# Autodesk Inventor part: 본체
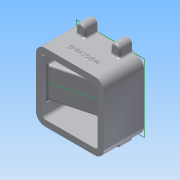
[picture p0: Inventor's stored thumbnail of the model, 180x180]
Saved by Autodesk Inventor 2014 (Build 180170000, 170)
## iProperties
Created: 2018-01
Part Number: 본체
Material: 알루미늄 6061
Document SubType Name: Modeling
Designer: net
Mass: 998.942 g
Surface Area: 839.391 cm^2
Volume: 368.613 cm^3
Density: 2.71 g/cm^3
Appearance: 알루미늄 - 평지
Author: net
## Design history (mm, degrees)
sketch "스케치1"
  geometry: L1 (-55, -55)-(55, -55); L2 (55, -55)-(55, 55); L3 (55, 55)-(-55, 55); L4 (-55, 55)-(-55, -55); L5 (-55, -55)-(55, 55); L6 (55, -55)-(-55, 55); 1 further point
  constraints: 12 end point, 2 midpoint, 2 parallel, 1 horizontal, 1 perpendicular
  dimensions: "d0" = 110 distance of L3.end L2.end; "d1" = 110 distance of L2.end L1.end
extrude "돌출1" new body sketch "스케치1" distance "d2" = 65; taper "d3" = 0 deg
sketch "스케치2"
  geometry: L1 (55, 55)-(-55, 55) reference; L2 (-55, 55)-(-55, -55) reference; L3 (-55, -55)-(55, -55) reference; L4 (55, -55)-(55, 55) reference; 1 further point
sketch "스케치3"
  geometry: L1 (-45, -45)-(45, -45); L2 (45, -45)-(45, 45); L3 (45, 45)-(-45, 45); L4 (-45, 45)-(-45, -45); L5 (-45, -45)-(45, 45); L6 (45, -45)-(-45, 45); 1 further point
  constraints: 12 end point, 2 midpoint, 2 parallel, 1 horizontal, 1 perpendicular
  dimensions: "d4" = 90 distance of L3.end L2.end; "d5" = 90 distance of L2.end L1.end
extrude "돌출2" cut sketch "스케치3" distance "d6" = 65; taper "d7" = 0 deg
sketch "스케치4"
  geometry: L1 (55, 55)-(-55, 55) reference; L2 (-55, 55)-(-55, -55) reference; L3 (-55, -55)-(55, -55) reference; L4 (-55, 0)-(-55, 25); L5 (-35.5, 65)-(-35.5, 55); L6 (-20.5, 65)-(-20.5, 55); L7 (0, 55)-(0, -55); L8 (-28, 65)-(28, 65); L9 (20.5, 65)-(20.5, 55); L10 (35.5, 65)-(35.5, 55); L11 (-55, -55)-(-28, -55); L12 (-28, -55)-(-28, -65); L13 (-35.5, -65)-(-35.5, -55); L14 (-20.5, -65)-(-20.5, -55); L15 (35.5, -65)-(35.5, -55); L16 (20.5, -65)-(20.5, -55); A1 r 7.5 centre (-28, 65) between (-20.5, 65) and (-35.5, 65); A2 r 7.5 centre (28, 65) between (35.5, 65) and (20.5, 65); A3 r 7.5 centre (-28, -65) between (-35.5, -65) and (-20.5, -65); A4 r 7.5 centre (28, -65) between (20.5, -65) and (35.5, -65); 1 further point
  constraints: 26 end point, 11 point on line, 8 point on circle, 8 tangent, 6 perpendicular, 4 centre point, 3 midpoint, 3 parallel, 2 coincident
  dimensions: "d9" = 25 distance of L4.start L4.end; "d11" = 27 distance from line of L2 L8.start; "d12" = 7.5 radius of A1; "d13" = 10 distance of L6.start L6.end; "d14" = 56 distance of L8.start L8.end; "d15" = 15 diameter of A2; "d16" = 27 distance of L2.end L11.end; "d17" = 10 distance of L11.end L12.end; "d18" = 15 diameter of A3; "d20" = 15 diameter of A4
extrude "돌출3" join sketch "스케치4" distance "d21" = 20; taper "d22" = 0 deg
sketch "스케치5"
  geometry: L1 (-45, 0)-(-45, 65) reference; L2 (-45, 8.564)-(35, 30); L3 (-45, 8.564)-(-45, 65); L4 (55, 0)-(-55, 0) reference; L5 (-45, 8.564)-(-55, 8.564); L6 (-55, 8.564)-(-55, 26.564); L7 (-55, 26.564)-(-45, 26.564); L8 (-45, 26.564)-(-6.286, 36.938); L9 (-6.286, 36.938)-(-6.286, 65); L10 (-45, 65)-(35, 65); L11 (35, 65)-(35, 30); 2 further points
  constraints: 18 end point, 3 perpendicular, 3 point on line, 2 parallel, 1 collinear
  dimensions: "d23" = 105 deg angle of L1 L2; "d25" = 18 distance of L5.end L6.end; "d26" = 75 deg angle of L1 L8 (derived); "d28" = 20 distance of point (55, 65) L10.end; "d29" = 30 distance from line of L4 L2.end
extrude "돌출4" join sketch "스케치5" stored distance "d30" = 50; taper "d31" = 0 deg
sketch "스케치6"
  geometry: 1 further point
sketch "스케치7"
  geometry: L1 (0, 65)-(110, 65) reference; C1 r 7.5 at (55, 65); 1 further point
  constraints: 1 centre point, 1 midpoint
  dimensions: "d32" = 15 diameter of C1
extrude "돌출5" cut sketch "스케치7" distance "d33" = 19; taper "d34" = 0 deg
sketch "스케치8"
  geometry: L1 (47.5, 65)-(62.5, 65) reference; A1 r 7.5 centre (55, 65) between (47.5, 65) and (62.5, 65) reference; 1 further point
sketch "스케치9"
  geometry: L1 (47.5, 65)-(62.5, 65) reference; C1 r 16 at (55, 65); A1 r 7.5 centre (55, 65) between (47.5, 65) and (62.5, 65) reference; 1 further point
  constraints: 1 centre point, 1 coincident
  dimensions: "d36" = 32 diameter of C1
extrude "돌출6" cut sketch "스케치9" distance "d37" = 14; taper "d38" = 0 deg
extrude "돌출7" cut sketch "스케치8" distance "d39" = 14; taper "d40" = 0 deg
sketch "스케치10"
  geometry: L1 (39, 65)-(71, 65) reference; C1 r 20 at (55, 65); A1 r 16 centre (55, 65) between (39, 65) and (71, 65) reference; 1 further point
  constraints: 1 centre point, 1 coincident
  dimensions: "d41" = 40 diameter of C1
extrude "돌출8" cut sketch "스케치10" distance "d42" = 47; taper "d43" = 0 deg
sketch "스케치11"
  geometry: L1 (39, 65)-(71, 65) reference; A1 r 16 centre (55, 65) between (39, 65) and (71, 65) reference; 1 further point
extrude "돌출9" cut sketch "스케치11" distance "d44" = 47; taper "d45" = 0 deg
sketch "스케치14"
  geometry: 1 further point
node "작업 평면3"
sketch "스케치16"
  geometry: 1 further point
sketch "스케치17"
  geometry: L1 (3.5, 15)-(40.5, 15); L2 (40.5, 15)-(40.5, -15); L3 (40.5, -15)-(3.5, -15); L4 (3.5, -15)-(3.5, 15); L5 (3.5, 15)-(40.5, -15); L6 (40.5, 15)-(3.5, -15); 1 further point
  constraints: 12 end point, 2 midpoint, 2 parallel, 1 horizontal, 1 perpendicular
  dimensions: "d52" = 37 distance of L2.end L3.end; "d53" = 30 distance of L1.end L2.end
extrude "돌출11" cut sketch "스케치17" distance "d54" = 13; taper "d55" = 0 deg; dims "d56" = 30, "d57" = 0
sketch "스케치18"
  geometry: 1 further point
sketch "스케치19"
  geometry: L1 (-18.5, 32)-(-18.5, 51.771) reference; L2 (-18.5, 32)-(-18.5, 37.747); L3 (-18.5, 37.747)-(-55, 27.967); L4 (-18.5, 37.747)-(-55, 27.967); L5 (-18.5, 51.771)-(18.5, 51.771) reference; L6 (-18.5, 32)-(-18.5, 51.771) reference; L7 (-18.5, 32)-(18.5, 32) reference; L8 (18.5, 32)-(18.5, 51.771) reference; L9 (18.5, 32)-(18.5, 30.568); L10 (18.5, 30.568)-(-55, 9.967); L11 (-55, 27.967)-(-55, 9.967); L12 (-18.5, 32)-(18.5, 32); L13 (-55, 27.967)-(-18.5, 37.747); L14 (-18.5, 32)-(-18.5, 37.747); L15 (-18.5, 32)-(18.5, 32); L16 (18.5, 32)-(18.5, 30.568); L17 (18.5, 30.568)-(-55, 9.967); L18 (-55, 9.967)-(-55, 27.967); 1 further point
  constraints: 26 end point, 7 collinear, 2 perpendicular
  node "투영된 루프2"
sketch "스케치20"
  geometry: C1 r 15 at (55, 65); A1 r 20 centre (55, 65) between (35, 65) and (75, 65) reference; 1 further point
  constraints: 1 centre point, 1 coincident
  dimensions: "d58" = 20 radius of A1 (derived); "d59" = 30 diameter of C1 (derived)
extrude "돌출12" cut sketch "스케치20" distance "d60" = 5; taper "d61" = 0 deg
extrude "돌출13" cut sketch "스케치19" stored distance "d62" = 15; taper "d63" = 0 deg
sketch "스케치21"
  geometry: L1 (3.5, 7.5)-(40.5, 7.5) reference; L2 (40.5, 15)-(40.5, 7.5) reference; L3 (3.5, 15)-(40.5, 15) reference; L4 (3.5, 7.5)-(3.5, 15) reference; 1 further point
sketch "스케치22"
  geometry: L1 (40.5, -7.5)-(3.5, -7.5) reference; L2 (3.5, -15)-(3.5, -7.5) reference; L3 (40.5, -15)-(3.5, -15) reference; L4 (40.5, -7.5)-(40.5, -15) reference; 1 further point
extrude "돌출14" cut sketch "스케치21" stored distance "d64" = 15; taper "d65" = 0 deg
sketch "스케치23"
  geometry: L1 (35, 30)-(-45, 8.564) reference; L2 (-55, 0)-(-55, 65) reference; L3 (18.5, 30.568)-(-18.5, 20.197) reference; 1 further point
sketch "스케치24"
  geometry: L1 (0, 22.5)-(0, 0) reference; L2 (0, 22.5)-(-38.426, 22.5) reference; L3 (-38.426, 22.5)-(-38.426, 15) reference; L4 (-38.426, 15)-(-76.333, 15) reference; L5 (-76.333, 0)-(-76.333, 15) reference; L6 (-76.333, 0)-(0, 0) reference; 1 further point
sketch "스케치25"
  geometry: L1 (47.5, 9.967)-(47.5, 27.967) reference; L2 (47.5, 27.967)-(62.5, 27.967) reference; L3 (62.5, 27.967)-(62.5, 9.967) reference; L4 (62.5, 9.967)-(47.5, 9.967) reference; L5 (55, 27.967)-(55, 9.967); L6 (70, 9.967)-(40, 9.967); L7 (40, 9.967)-(40, 27.967); L8 (40, 27.967)-(70, 27.967); L9 (70, 27.967)-(70, 9.967); L10 (70, 9.967)-(40, 27.967); L11 (40, 9.967)-(70, 27.967); 2 further points
  constraints: 14 end point, 5 midpoint, 2 parallel, 1 horizontal, 1 perpendicular, 1 point on line
  dimensions: "d66" = 30 distance of L7.end L8.end
extrude "돌출15" cut sketch "스케치25" stored distance "d67" = 15; taper "d68" = 0 deg
sketch "스케치26"
  geometry: L1 (36.5, 7.5)-(36.5, 0) reference; L2 (0, 7.5)-(36.5, 7.5) reference; L3 (0, 0)-(0, 7.5) reference; L4 (0, 0)-(36.5, 0) reference; 1 further point
extrude "돌출16" cut sketch "스케치26" stored distance "d69" = 15; taper "d70" = 0 deg
sketch "스케치27"
  geometry: L1 (64.22, 7.5)-(64.22, 0) reference; L2 (0, 7.5)-(64.22, 7.5) reference; L3 (0, 0)-(0, 7.5) reference; L4 (64.22, 0)-(0, 0) reference; 1 further point
extrude "돌출17" cut sketch "스케치27" stored distance "d71" = 15; taper "d72" = 0 deg
sketch "스케치28"
  geometry: L1 (31.22, -7.5)-(31.22, -15) reference; L2 (40.5, -15)-(31.22, -15) reference; L3 (40.5, -7.5)-(40.5, -15) reference; L4 (40.5, -7.5)-(31.22, -7.5) reference; 1 further point
extrude "돌출18" cut sketch "스케치22" stored distance "d73" = 15; taper "d74" = 0 deg
sketch "스케치29"
  geometry: A1 r 7.5 centre (-28, -65) between (-35.5, -65) and (-20.5, -65) reference; A2 r 7.5 centre (28, -65) between (20.5, -65) and (35.5, -65) reference; A3 r 7.5 centre (28, 65) between (35.5, 65) and (20.5, 65) reference; A4 r 7.5 centre (-28, 65) between (-20.5, 65) and (-35.5, 65) reference; 1 further point
hole "구멍1" sketch "스케치29" at (-28, 65), (28, 65), (28, -65), (-28, -65) diameter "d75" = 3.242; stored, may be unused: countersink angle "d79" = 90 deg, drill point angle "d81" = 118 deg; dims "d76" = 9, "d77" = 4, "d78" = 2, "d80" = 11
fillet "모깎기1" dims "d82" = 15
fillet "모깎기2" dims "d83" = 3
fillet "모깎기3" dims "d84" = 1
fillet "모깎기4" dims "d85" = 3
fillet "모깎기5" dims "d86" = 5
fillet "모깎기6" dims "d87" = 3
fillet "모깎기7" dims "d88" = 3
chamfer "모따기1" distance "d89" = 1; stored, may be unused: second distance "d90" = 2, angle "d91" = 45 deg
chamfer "모따기2" distance "d92" = 1; stored, may be unused: second distance "d93" = 2, angle "d94" = 45 deg
sketch "스케치30"
  geometry: L1 (-17.958, -22.32)-(59.863, -22.32); L2 (59.863, -22.32)-(59.863, -62.588); L3 (59.863, -62.588)-(-17.958, -62.588); L4 (-17.958, -62.588)-(-17.958, -22.32); 1 further point
  constraints: 2 other
feature "엠보싱1" sketch "스케치30" dims "d4" = 90, "d5" = 90, "d95" = 0.5, "d96" = 0
fillet "모깎기10" dims "d99" = 3
node "솔리드1"
